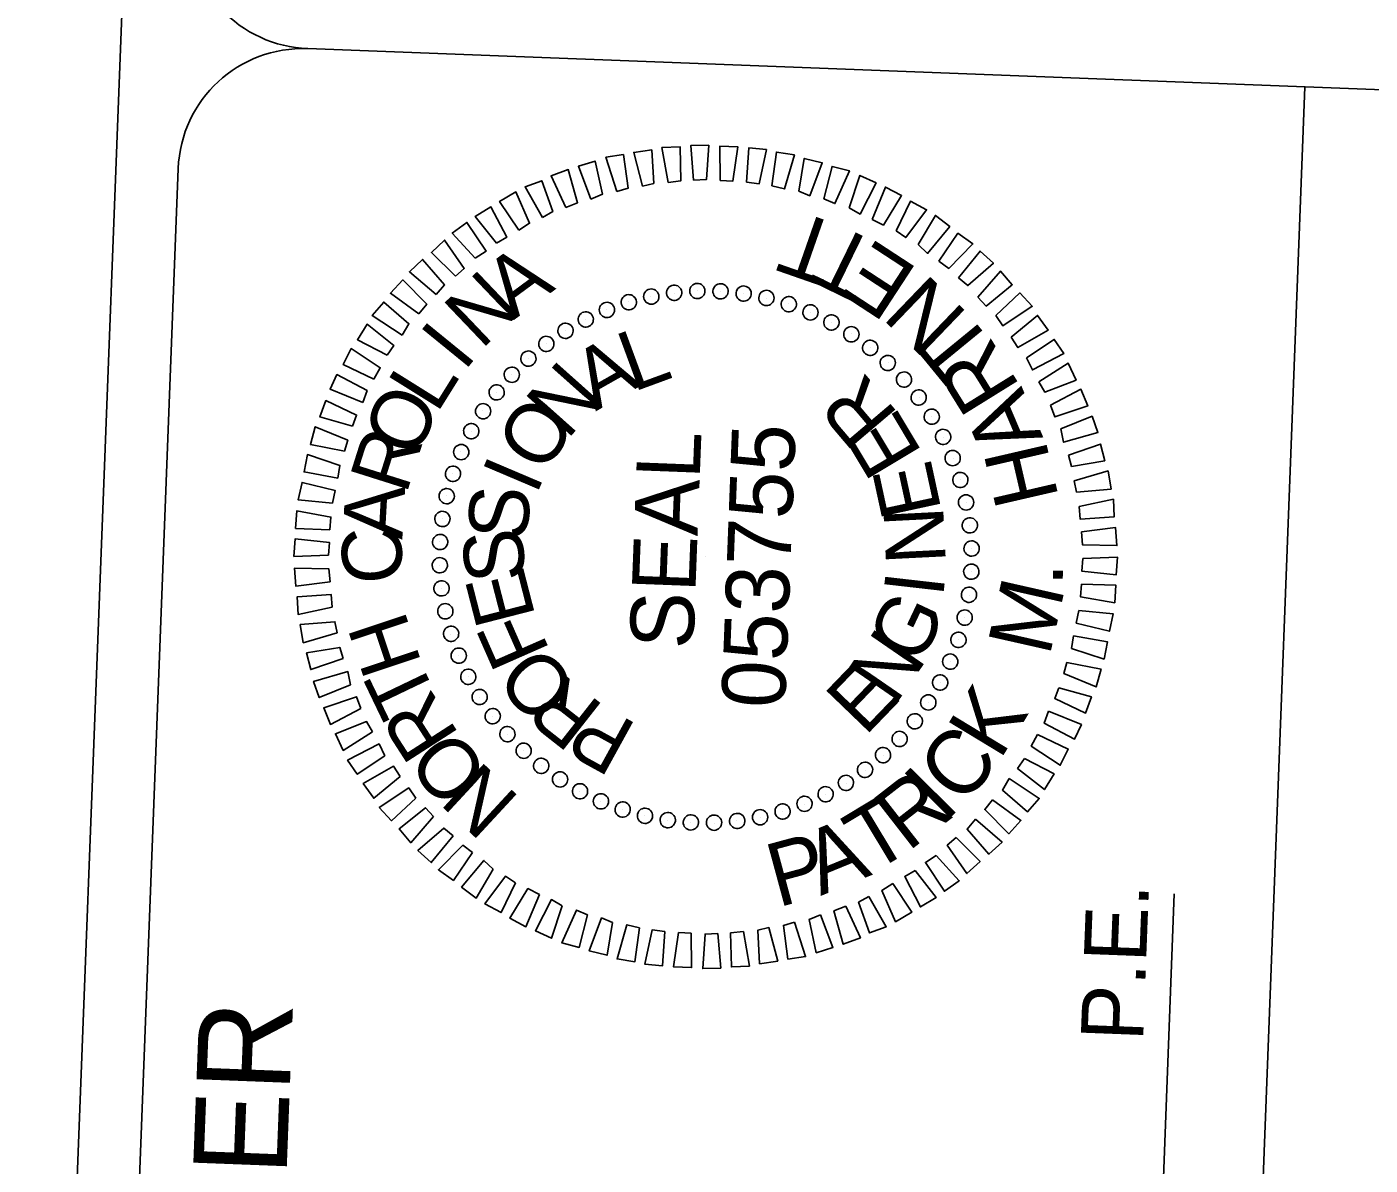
# Model space of a CAD drawing. Extents: x 2094564 to 2100382, y 679033 to 692366.
# Drawn here: x 2099233 to 2099771, y 689098 to 689554 of the extents above; entities that cross this region are included whole.
import ezdxf

# ---------------------------------------------------------------- set-up
doc = ezdxf.new("R2010")
doc.units = 0
doc.layers.add('Prop Horizontal Alignment Direction Label', color=7, linetype='Continuous')
doc.layers.add('Sheet PE Seal Cell', color=7, linetype='Continuous')

msp = doc.modelspace()

# ---------------------------------------------------------------- linework, layer by layer
at = {"layer": 'Prop Horizontal Alignment Direction Label'}
for p, q in [((2099030, 683278.86), (2099302.1, 690373.65)), ((2100144.8, 689514.58), (2099345.38, 689545.23)), ((2099702.69, 688427.37), (2099744.97, 689529.91)), ((2099255.22, 688499.07), (2099293.5, 689497.19)), ((2099664.97, 688485.83), (2099692.61, 689206.55))]:
    msp.add_line(p, q, dxfattribs=at)
for centre, start, end in [((2099347.3, 689595.2), 177.8037, 267.8037), ((2099343.47, 689495.27), 87.8037, 177.8037)]:
    msp.add_arc(centre, 50, start, end, dxfattribs=at)
at = {"layer": 'Sheet PE Seal Cell'}
for p, q in [((2099482.93, 689445.96), (2099482.93, 689445.96)), ((2099492.34, 689447.3), (2099492.34, 689447.3)), ((2099501.52, 689448.23), (2099501.52, 689448.23)), ((2099510.87, 689448.08), (2099510.87, 689448.08)), ((2099520.19, 689447.08), (2099520.19, 689447.08)), ((2099529.26, 689445.25), (2099529.26, 689445.25)), ((2099465.29, 689440.68), (2099465.29, 689440.68)), ((2099473.91, 689443.75), (2099473.91, 689443.75)), ((2099538.11, 689442.99), (2099538.11, 689442.99)), ((2099546.91, 689439.68), (2099546.91, 689439.68)), ((2099456.84, 689436.75), (2099456.84, 689436.75)), ((2099555.26, 689435.53), (2099555.26, 689435.53)), ((2099448.59, 689432.18), (2099448.59, 689432.18)), ((2099563.38, 689430.97), (2099563.38, 689430.97)), ((2099440.95, 689427.16), (2099440.95, 689427.16)), ((2099570.82, 689425.37), (2099570.82, 689425.37)), ((2099433.7, 689421.05), (2099433.7, 689421.05)), ((2099578.03, 689419.35), (2099578.03, 689419.35)), ((2099427.08, 689414.72), (2099427.08, 689414.72)), ((2099584.37, 689412.72), (2099584.37, 689412.72)), ((2099421.06, 689407.5), (2099421.06, 689407.5)), ((2099590.47, 689405.47), (2099590.47, 689405.47)), ((2099415.46, 689400.06), (2099415.46, 689400.06)), ((2099595.49, 689397.84), (2099595.49, 689397.84)), ((2099410.89, 689391.94), (2099410.89, 689391.94)), ((2099600.07, 689389.58), (2099600.07, 689389.58)), ((2099406.74, 689383.6), (2099406.74, 689383.6)), ((2099604, 689381.14), (2099604, 689381.14)), ((2099403.43, 689374.79), (2099403.43, 689374.79)), ((2099607.07, 689372.51), (2099607.07, 689372.51)), ((2099401.18, 689365.95), (2099401.18, 689365.95)), ((2099609.27, 689363.5), (2099609.27, 689363.5)), ((2099399.34, 689356.87), (2099399.34, 689356.87)), ((2099610.61, 689354.09), (2099610.61, 689354.09)), ((2099398.35, 689347.56), (2099398.35, 689347.56)), ((2099611.54, 689344.91), (2099611.54, 689344.91)), ((2099398.2, 689338.2), (2099398.2, 689338.2)), ((2099504.87, 689341.56), (2099504.87, 689341.56)), ((2099611.39, 689335.56), (2099611.39, 689335.56)), ((2099399.12, 689329.02), (2099399.12, 689329.02)), ((2099610.4, 689326.24), (2099610.4, 689326.24)), ((2099400.46, 689319.62), (2099400.46, 689319.62)), ((2099608.56, 689317.16), (2099608.56, 689317.16)), ((2099402.67, 689310.6), (2099402.67, 689310.6)), ((2099606.31, 689308.32), (2099606.31, 689308.32)), ((2099405.74, 689301.98), (2099405.74, 689301.98)), ((2099602.99, 689299.51), (2099602.99, 689299.51)), ((2099409.67, 689293.53), (2099409.67, 689293.53)), ((2099598.84, 689291.17), (2099598.84, 689291.17)), ((2099414.24, 689285.28), (2099414.24, 689285.28)), ((2099594.28, 689283.05), (2099594.28, 689283.05)), ((2099419.27, 689277.64), (2099419.27, 689277.64)), ((2099588.68, 689275.61), (2099588.68, 689275.61)), ((2099425.37, 689270.39), (2099425.37, 689270.39)), ((2099582.66, 689268.4), (2099582.66, 689268.4)), ((2099431.71, 689263.77), (2099431.71, 689263.77)), ((2099576.04, 689262.06), (2099576.04, 689262.06)), ((2099438.92, 689257.75), (2099438.92, 689257.75)), ((2099446.36, 689252.15), (2099446.36, 689252.15)), ((2099561.15, 689250.93), (2099561.15, 689250.93)), ((2099568.78, 689255.96), (2099568.78, 689255.96)), ((2099454.48, 689247.58), (2099454.48, 689247.58)), ((2099552.89, 689246.36), (2099552.89, 689246.36)), ((2099462.83, 689243.43), (2099462.83, 689243.43)), ((2099471.63, 689240.12), (2099471.63, 689240.12)), ((2099544.45, 689242.43), (2099544.45, 689242.43)), ((2099480.48, 689237.86), (2099480.48, 689237.86)), ((2099489.55, 689236.03), (2099489.55, 689236.03)), ((2099498.87, 689235.03), (2099498.87, 689235.03)), ((2099508.22, 689234.89), (2099508.22, 689234.89)), ((2099517.4, 689235.81), (2099517.4, 689235.81)), ((2099526.81, 689237.15), (2099526.81, 689237.15)), ((2099535.82, 689239.36), (2099535.82, 689239.36))]:
    msp.add_line(p, q, dxfattribs=at)
for points in [[(2099479.52, 689490.11), (2099476, 689503.64), (2099483.26, 689504.64), (2099484.03, 689491.21)], [(2099489.78, 689491.63), (2099487.34, 689505.55), (2099494.58, 689505.91), (2099494.91, 689492.29)], [(2099500.03, 689492.52), (2099498.86, 689506.38), (2099506.09, 689506.53), (2099505.14, 689492.74)], [(2099510.65, 689492.32), (2099510.54, 689506.15), (2099517.76, 689505.87), (2099515.75, 689492.12)], [(2099521.26, 689491.7), (2099522.21, 689505.49), (2099529.2, 689504.79), (2099526.34, 689491.08)], [(2099531.41, 689490.25), (2099533.21, 689503.79), (2099540.39, 689502.66), (2099536.47, 689488.99)], [(2099458.9, 689484.95), (2099453.88, 689498.11), (2099460.55, 689500.2), (2099463.45, 689486.9)], [(2099469.23, 689487.95), (2099464.86, 689501.73), (2099471.92, 689502.74), (2099473.74, 689489.27)], [(2099542.18, 689488.13), (2099544.38, 689501.23), (2099551.54, 689499.47), (2099546.57, 689486.26)], [(2099448.78, 689481.51), (2099442.89, 689494.28), (2099449.79, 689496.78), (2099453.53, 689483.45)], [(2099552.26, 689484.98), (2099555.53, 689498.04), (2099562.48, 689496.29), (2099556.66, 689483.11)], [(2099562.33, 689481.41), (2099566.66, 689494.43), (2099573.14, 689491.41), (2099566.7, 689478.9)], [(2099429.93, 689472.45), (2099422.29, 689484.01), (2099428.82, 689487.8), (2099434.29, 689475.26)], [(2099439.48, 689477.61), (2099432.51, 689489.79), (2099439.2, 689492.3), (2099443.62, 689480.01)], [(2099571.51, 689476.8), (2099576.9, 689489.78), (2099583.36, 689486.34), (2099576.1, 689474.5)], [(2099581.12, 689472.18), (2099586.89, 689484.08), (2099593.35, 689480.64), (2099585.05, 689469.48)], [(2099421.01, 689467.26), (2099412.49, 689478.01), (2099418.81, 689481.81), (2099425.14, 689469.66)], [(2099590.05, 689466.73), (2099596.88, 689478.38), (2099602.66, 689473.91), (2099593.75, 689463.19)], [(2099412.49, 689461.21), (2099403.31, 689471.34), (2099409.21, 689475.58), (2099416.85, 689464.02)], [(2099404.56, 689454.07), (2099394.93, 689463.58), (2099400.22, 689468.48), (2099408.08, 689457.13)], [(2099598.3, 689460.04), (2099605.96, 689471.23), (2099611.97, 689466.96), (2099602.23, 689457.12)], [(2099396.83, 689446.71), (2099386.12, 689455.84), (2099391.42, 689460.74), (2099400.17, 689450.62)], [(2099606.13, 689453.36), (2099614.83, 689464.08), (2099620.17, 689459.2), (2099609.84, 689450.24)], [(2099613.91, 689445.62), (2099623.03, 689456.11), (2099627.71, 689450.62), (2099617.18, 689442.09)], [(2099389.94, 689438.89), (2099378.56, 689447.2), (2099383.44, 689452.54), (2099393.07, 689442.82)], [(2099621.07, 689438.32), (2099630.78, 689447.31), (2099635.68, 689442.02), (2099623.89, 689434.18)], [(2099383.24, 689430.43), (2099371.2, 689438.34), (2099375.88, 689443.69), (2099385.96, 689435.01)], [(2099377.18, 689422.37), (2099365.3, 689428.57), (2099369.15, 689434.8), (2099379.89, 689426.31)], [(2099627.33, 689429.58), (2099637.87, 689438.32), (2099642.11, 689432.41), (2099629.94, 689425.44)], [(2099633.39, 689421.26), (2099644.52, 689428.71), (2099648.35, 689423.03), (2099635.76, 689416.49)], [(2099371.93, 689412.79), (2099359.6, 689418.58), (2099362.83, 689425.05), (2099374.44, 689417.37)], [(2099638.34, 689411.72), (2099650.11, 689419.13), (2099653.26, 689412.42), (2099640.74, 689407.59)], [(2099367.52, 689403.39), (2099354.33, 689408.79), (2099357.11, 689414.63), (2099369.2, 689408.22)], [(2099643.09, 689402.39), (2099655.24, 689408.73), (2099657.96, 689402.03), (2099644.82, 689397.65)], [(2099363.34, 689393.98), (2099350.29, 689397.67), (2099352.67, 689404.17), (2099364.99, 689398.38)], [(2099647.19, 689392.88), (2099659.72, 689397.93), (2099662.02, 689391.46), (2099648.26, 689387.52)], [(2099360.18, 689383.89), (2099346.46, 689386.55), (2099348.44, 689393.7), (2099361.42, 689388.31)], [(2099650.19, 689382.34), (2099663.12, 689386.74), (2099664.77, 689380.08), (2099651.5, 689377.83)], [(2099357.43, 689373.15), (2099343.92, 689375.59), (2099345.25, 689382.55), (2099358.27, 689378.23)], [(2099652.56, 689372.04), (2099666.11, 689375.99), (2099667.32, 689368.71), (2099653.45, 689367.54)], [(2099355.34, 689363.03), (2099341.57, 689364.41), (2099343.12, 689371.36), (2099356.39, 689368.09)], [(2099654.5, 689361.76), (2099668.22, 689364.64), (2099668.59, 689357.61), (2099654.94, 689356.64)], [(2099354.3, 689352.43), (2099340.5, 689352.96), (2099340.98, 689359.96), (2099354.71, 689357.52)], [(2099655.39, 689351.52), (2099669.07, 689353.33), (2099669.64, 689346.08), (2099655.83, 689346.4)], [(2099353.7, 689342.25), (2099339.85, 689341.72), (2099340.33, 689348.72), (2099354.1, 689347.34)], [(2099354.35, 689331.59), (2099340.67, 689329.78), (2099340.1, 689337.03), (2099353.91, 689336.71)], [(2099656.04, 689340.86), (2099669.88, 689341.39), (2099669.4, 689334.4), (2099655.63, 689335.77)], [(2099355.23, 689321.35), (2099341.51, 689318.47), (2099341.15, 689325.51), (2099354.79, 689326.47)], [(2099655.44, 689330.68), (2099669.24, 689330.15), (2099668.76, 689323.15), (2099655.03, 689325.59)], [(2099357.18, 689311.07), (2099343.63, 689307.12), (2099342.42, 689314.4), (2099356.29, 689315.57)], [(2099654.39, 689320.09), (2099668.16, 689318.71), (2099666.62, 689311.75), (2099653.35, 689315.02)], [(2099652.3, 689309.96), (2099665.82, 689307.53), (2099664.49, 689300.56), (2099651.47, 689304.89)], [(2099359.55, 689300.77), (2099346.62, 689296.37), (2099344.96, 689303.03), (2099358.23, 689305.29)], [(2099649.55, 689299.22), (2099663.27, 689296.56), (2099661.3, 689289.41), (2099648.32, 689294.8)], [(2099362.55, 689290.24), (2099350.02, 689285.19), (2099347.72, 689291.65), (2099361.48, 689295.59)], [(2099646.4, 689289.13), (2099659.44, 689285.44), (2099657.07, 689278.94), (2099644.74, 689284.73)], [(2099366.65, 689280.72), (2099354.5, 689274.38), (2099351.78, 689281.08), (2099364.92, 689285.47)], [(2099642.21, 689279.72), (2099655.4, 689274.33), (2099652.63, 689268.48), (2099640.54, 689274.9)], [(2099371.39, 689271.39), (2099359.63, 689263.98), (2099356.48, 689270.69), (2099369, 689275.53)], [(2099637.81, 689270.32), (2099650.14, 689264.53), (2099646.91, 689258.06), (2099635.3, 689265.74)], [(2099376.34, 689261.85), (2099365.21, 689254.41), (2099361.39, 689260.08), (2099373.98, 689266.62)], [(2099382.41, 689253.53), (2099371.86, 689244.79), (2099367.62, 689250.7), (2099379.8, 689257.67)], [(2099632.55, 689260.74), (2099644.44, 689254.54), (2099640.58, 689248.31), (2099629.85, 689256.8)], [(2099626.5, 689252.68), (2099638.53, 689244.78), (2099633.86, 689239.43), (2099623.77, 689248.11)], [(2099388.66, 689244.79), (2099378.96, 689235.8), (2099374.06, 689241.1), (2099385.84, 689248.94)], [(2099395.83, 689237.5), (2099386.7, 689227), (2099382.02, 689232.5), (2099392.56, 689241.02)], [(2099619.8, 689244.22), (2099631.18, 689235.91), (2099626.29, 689230.57), (2099616.67, 689240.3)], [(2099612.91, 689236.4), (2099623.61, 689227.27), (2099618.32, 689222.37), (2099609.57, 689232.49)], [(2099403.61, 689229.75), (2099394.9, 689219.03), (2099389.56, 689223.91), (2099399.9, 689232.87)], [(2099411.43, 689223.07), (2099403.77, 689211.89), (2099397.77, 689216.16), (2099407.51, 689225.99)], [(2099605.18, 689229.04), (2099614.81, 689219.53), (2099609.52, 689214.63), (2099601.66, 689225.99)], [(2099419.68, 689216.38), (2099412.86, 689204.73), (2099407.07, 689209.21), (2099415.99, 689219.92)], [(2099597.25, 689221.9), (2099606.43, 689211.77), (2099600.53, 689207.53), (2099592.89, 689219.09)], [(2099428.62, 689210.93), (2099422.85, 689199.03), (2099416.39, 689202.47), (2099424.68, 689213.64)], [(2099588.73, 689215.85), (2099597.24, 689205.1), (2099590.93, 689201.3), (2099584.59, 689213.46)], [(2099438.22, 689206.31), (2099432.84, 689193.33), (2099426.37, 689196.77), (2099433.63, 689208.61)], [(2099579.81, 689210.66), (2099587.44, 689199.1), (2099580.92, 689195.31), (2099575.45, 689207.85)], [(2099447.4, 689201.71), (2099443.08, 689188.69), (2099436.6, 689191.7), (2099443.03, 689204.21)], [(2099570.25, 689205.5), (2099577.23, 689193.32), (2099570.54, 689190.82), (2099566.12, 689203.11)], [(2099457.47, 689198.13), (2099454.21, 689185.07), (2099447.26, 689186.83), (2099453.08, 689200)], [(2099467.56, 689194.98), (2099465.36, 689181.88), (2099458.19, 689183.64), (2099463.17, 689196.85)], [(2099550.83, 689198.16), (2099555.86, 689185), (2099549.18, 689182.92), (2099546.29, 689196.21)], [(2099560.96, 689201.6), (2099566.85, 689188.83), (2099559.95, 689186.33), (2099556.21, 689199.66)], [(2099478.33, 689192.86), (2099476.53, 689179.32), (2099469.34, 689180.45), (2099473.27, 689194.12)], [(2099488.48, 689191.41), (2099487.52, 689177.63), (2099480.53, 689178.32), (2099483.4, 689192.03)], [(2099519.95, 689191.48), (2099522.4, 689177.56), (2099515.15, 689177.2), (2099514.82, 689190.83)], [(2099530.22, 689193), (2099533.74, 689179.47), (2099526.47, 689178.47), (2099525.71, 689191.9)], [(2099540.51, 689195.16), (2099544.87, 689181.38), (2099537.82, 689180.38), (2099535.99, 689193.84)], [(2099499.09, 689190.79), (2099499.19, 689176.97), (2099491.97, 689177.24), (2099493.99, 689190.99)], [(2099509.71, 689190.6), (2099510.88, 689176.73), (2099503.65, 689176.58), (2099504.6, 689190.37)]]:
    msp.add_lwpolyline(points, close=True, dxfattribs=at)
for centre, major_axis in [((2099492.24, 689447.4), (-0.36, 3.04)), ((2099501.51, 689448.09), (-0.1, 3.06)), ((2099510.81, 689447.98), (0.17, 3.06)), ((2099520.06, 689447.06), (0.44, 3.03)), ((2099474.05, 689443.59), (-0.88, 2.93)), ((2099483.06, 689445.89), (-0.63, 3)), ((2099529.2, 689445.33), (0.7, 2.98)), ((2099538.15, 689442.82), (0.96, 2.91)), ((2099456.8, 689436.69), (-1.38, 2.73)), ((2099465.28, 689440.52), (-1.14, 2.84)), ((2099546.85, 689439.53), (1.21, 2.81)), ((2099448.69, 689432.14), (-1.61, 2.6)), ((2099555.23, 689435.5), (1.45, 2.7)), ((2099563.23, 689430.75), (1.68, 2.56)), ((2099441.01, 689426.9), (-1.83, 2.45)), ((2099570.78, 689425.32), (1.89, 2.4)), ((2099433.82, 689421.01), (-2.04, 2.28)), ((2099427.16, 689414.52), (-2.23, 2.09)), ((2099577.83, 689419.26), (2.09, 2.23)), ((2099584.32, 689412.61), (2.28, 2.04)), ((2099421.1, 689407.47), (-2.4, 1.89)), ((2099590.21, 689405.41), (2.45, 1.83)), ((2099415.67, 689399.92), (-2.56, 1.68)), ((2099595.45, 689397.73), (2.6, 1.61)), ((2099410.93, 689391.92), (-2.7, 1.45)), ((2099600.01, 689389.62), (2.73, 1.38)), ((2099406.9, 689383.54), (-2.81, 1.21)), ((2099603.83, 689381.15), (2.84, 1.14)), ((2099403.61, 689374.84), (-2.91, 0.96)), ((2099606.91, 689372.37), (2.93, 0.88)), ((2099401.09, 689365.89), (-2.98, 0.7)), ((2099609.2, 689363.36), (3, 0.63)), ((2099399.37, 689356.75), (-3.03, 0.44)), ((2099610.71, 689354.18), (3.04, 0.36)), ((2099398.44, 689347.5), (-3.06, 0.17)), ((2099611.41, 689344.91), (3.06, 0.1)), ((2099398.33, 689338.2), (-3.06, -0.1)), ((2099611.29, 689335.61), (3.06, -0.17)), ((2099399.03, 689328.93), (-3.04, -0.36)), ((2099610.37, 689326.36), (3.03, -0.44)), ((2099400.53, 689319.75), (-3, -0.63)), ((2099608.64, 689317.22), (2.98, -0.7)), ((2099402.83, 689310.74), (-2.93, -0.88)), ((2099606.13, 689308.27), (2.91, -0.96)), ((2099405.9, 689301.97), (-2.84, -1.14)), ((2099602.84, 689299.57), (2.81, -1.21)), ((2099409.73, 689293.49), (-2.73, -1.38)), ((2099598.81, 689291.19), (2.7, -1.45)), ((2099414.28, 689285.38), (-2.6, -1.61)), ((2099594.06, 689283.2), (2.56, -1.68)), ((2099419.52, 689277.7), (-2.45, -1.83)), ((2099588.64, 689275.65), (2.4, -1.89)), ((2099425.41, 689270.51), (-2.28, -2.04)), ((2099431.91, 689263.85), (-2.09, -2.23)), ((2099582.57, 689268.6), (2.23, -2.09)), ((2099575.92, 689262.1), (2.04, -2.28)), ((2099438.96, 689257.79), (-1.89, -2.4)), ((2099568.72, 689256.21), (1.83, -2.45)), ((2099446.51, 689252.36), (-1.68, -2.56)), ((2099454.51, 689247.61), (-1.45, -2.7)), ((2099561.04, 689250.97), (1.61, -2.6)), ((2099462.88, 689243.58), (-1.21, -2.81)), ((2099544.46, 689242.59), (1.14, -2.84)), ((2099552.93, 689246.42), (1.38, -2.73)), ((2099471.58, 689240.3), (-0.96, -2.91)), ((2099480.54, 689237.78), (-0.7, -2.98)), ((2099526.67, 689237.22), (0.63, -3)), ((2099535.68, 689239.52), (0.88, -2.93)), ((2099489.67, 689236.05), (-0.44, -3.03)), ((2099498.93, 689235.13), (-0.17, -3.06)), ((2099508.22, 689235.02), (0.1, -3.06)), ((2099517.5, 689235.72), (0.36, -3.04))]:
    msp.add_ellipse(centre, major_axis=major_axis, ratio=0.999708, dxfattribs=at)

# ---------------------------------------------------------------- texts
at = {"layer": 'Prop Horizontal Alignment Direction Label'}
for s, height, p in [('P.E.', 24.997, (2099680.1, 689147.19)), (' HYDRAULICS ENGINEER', 37.5, (2099316.04, 688550.28))]:
    msp.add_text(s, height=height, rotation=87.8037, dxfattribs=at).set_placement(p)
at = {"layer": 'Sheet PE Seal Cell'}
for s, height, rotation, p in [('T', 25.49, 160.7594, (2099560.46, 689473.85)), ('T', 25.49, 153.9592, (2099575.73, 689466.34)), ('E', 25.49, 146.8498, (2099590.63, 689456.61)), ('A', 23.96, 36.4209, (2099427.91, 689436.38)), ('N', 23.96, 43.6226, (2099414.9, 689424.33)), ('N', 25.49, 136.124, (2099610.54, 689438.64)), ('I', 23.96, 50.8238, (2099407.97, 689415.45)), ('T', 25.49, 129.3238, (2099621.3, 689425.45)), ('L', 23.97, 20.2045, (2099475.71, 689407.53)), ('R', 25.49, 121.8435, (2099631.23, 689409.57)), ('A', 23.97, 29.564, (2099460.74, 689399.81)), ('N', 23.96, 48.2803, (2099449.24, 689388.13)), ('L', 23.96, 58.0246, (2099397.11, 689398.64)), ('R', 23.96, 130.2851, (2099582.55, 689398.55)), ('O', 23.96, 65.2249, (2099388.54, 689380.26)), ('A', 25.49, 113.0032, (2099640.18, 689389.35)), ('O', 23.96, 57.6372, (2099440.2, 689374.23)), ('E', 23.96, 120.9278, (2099591.95, 689383.09)), ('R', 23.96, 72.4248, (2099384.81, 689366.15)), ('053755', 25.492, 87.8037, (2099536.59, 689280.64)), ('SEAL', 25.492, 87.8037, (2099499.83, 689304.33)), ('H', 25.49, 103.0192, (2099646.42, 689365.16)), ('I', 23.96, 66.9933, (2099436.9, 689365.85)), ('E', 23.96, 102.2155, (2099599.37, 689360.26)), ('A', 23.96, 86.824, (2099383.28, 689348.35)), ('S', 23.96, 85.7041, (2099433.23, 689347.71)), ('N', 23.96, 92.8601, (2099601.11, 689339.14)), ('C', 23.96, 94.0236, (2099383.91, 689331.52)), ('S', 23.96, 95.0593, (2099432.85, 689332.41)), ('E', 23.96, 104.4148, (2099436.75, 689317.59)), ('I', 23.96, 83.5049, (2099599.93, 689324.94)), ('M', 25.49, 77.2556, (2099642.61, 689301.29)), ('.', 25.49, 88.7851, (2099647.88, 689329.64)), ('G', 23.96, 64.7939, (2099590.79, 689297.43)), ('H', 23.96, 108.4232, (2099391.16, 689298.92)), ('F', 23.96, 113.7707, (2099442.6, 689303.75)), ('N', 23.96, 55.4377, (2099580.62, 689281.66)), ('O', 23.96, 132.4849, (2099454.59, 689289.26)), ('E', 23.96, 46.0806, (2099568.66, 689269.36)), ('T', 23.96, 115.6235, (2099397.64, 689284.85)), ('R', 23.97, 141.8433, (2099464.71, 689281.43)), ('K', 25.49, 58.7713, (2099622.74, 689259.7)), ('R', 23.96, 122.8242, (2099406.43, 689270.05)), ('P', 23.97, 151.2026, (2099478.04, 689274.11)), ('C', 25.49, 49.1892, (2099607.47, 689241.22)), ('O', 23.96, 130.0254, (2099419.03, 689254.89)), ('N', 23.96, 137.2272, (2099430.98, 689244.65)), ('I', 25.49, 45.3872, (2099600.59, 689234.64)), ('R', 25.49, 37.907, (2099585.85, 689223.09)), ('T', 25.49, 31.1067, (2099571.26, 689214.33)), ('P', 25.49, 15.1571, (2099533.74, 689200.99)), ('A', 25.49, 22.2664, (2099550.92, 689205.64))]:
    msp.add_text(s, height=height, rotation=rotation, dxfattribs=at).set_placement(p)

doc.saveas('drawing.dxf')
